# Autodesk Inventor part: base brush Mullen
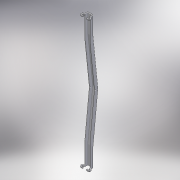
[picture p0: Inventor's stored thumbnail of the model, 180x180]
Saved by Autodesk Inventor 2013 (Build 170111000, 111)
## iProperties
Shininess: 20.0
Length Units: 11269
Angle Units: 11279
Time Units: 11290
Mass Units: 11283
Length Display Precision: 3
Angle Display Precision: 2
Created: 2002-03
Part Number: base brush Mullen
Document SubType Name: Modeling
Designer: =<Author>
Density: 1 g/cm^3
Material: Generic
Description: =<Part Number>
Density: 0.0
Volumn: 0.0
Area: 0.0
PropertySet Name: Model Information
Control State: 0
Master: False
Checked Out: True
Last Check In Date: 2008-10-15
Checked Out Date: 2008-10-15
Author: LAlexey
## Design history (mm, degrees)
sketch "Sketch1"
  geometry: L1 (0, 121.295)-(-5.969, 63.112); L2 (0, 3.705)-(-5.969, 61.888); L3 (0, -27.5)-(0, 3.705); L4 (0, -27.5)-(-4, -27.5); L5 (-4, -27.5)-(-4, -2.5); L6 (-4, -2.5)-(-10.557, 61.417); L7 (-4, 127.5)-(-10.557, 63.583); L8 (-4, 152.5)-(-4, 127.5); L9 (0, 152.5)-(-4, 152.5); L10 (0, 121.295)-(0, 152.5); A1 r 6 centre (0, 62.5) between (-5.969, 63.112) and (-5.969, 61.888); A2 r 10.612 centre (0, 62.5) between (-10.557, 63.583) and (-10.557, 61.417)
  constraints: 20 end point, 4 point on circle, 4 tangent, 4 vertical, 2 centre point, 2 collinear, 2 horizontal, 2 parallel, 1 concentric, 1 other
  dimensions: "d1" = 180 distance of L4.end L8.start; "d3" = 25 distance of L4.end L5.end; "d5" = 25 distance of L8.start L7.start; "d7" = 90 distance of L9.start A2.centre; "d9" = 6 radius of A1; "d11" = 4 distance of L4.end L3.start; "d13" = 4 horizontal distance of L7.start A2.centre
extrude "ExtrusionBlind1" new body sketch "Sketch1" distance "d14" = 8; taper "d15" = 0 deg
fillet "Fillet1" dims "d16" = 1.5
shell "Shell1" dims "d17" = 1
sketch "Sketch2"
  geometry: L1 (63, 6.982)-(63, 5.979); L2 (62, 6.982)-(62, 5.979); C1 r 6 at (62.5, 0); A1 r 6 centre (62.5, 0) between (63, 5.979) and (62, 5.979); A2 r 7 centre (62.5, 0) between (63, 6.982) and (62, 6.982)
  constraints: 4 end point, 4 point on circle, 3 centre point, 2 vertical, 1 coincident, 1 concentric
  dimensions: "d22" = 1 distance of L1.end L2.end; "d24" = 0.5 horizontal distance of L1.end A2.centre
extrude "ExtrusionThru1" cut sketch "Sketch2" stored distance "d25" = 0.13; taper "d26" = 0 deg
sketch "Sketch3"
  geometry: L1 (-8.5, -3.5)-(-6.5, -3.5); L2 (-8, 0)-(-7, 0); L3 (-8.5, -4.5)-(-6.5, -4.5); L4 (-6.5, -3.5)-(-6.5, -4.5); L5 (0, 0)-(-1, 0) reference; A1 r 1 centre (-8.5, -2.5) between (-8.5, -1.5) and (-8.5, -3.5); A2 r 1.5 centre (-8.5, 0) between (-8.5, -1.5) and (-7, 0); A3 r 0.5 centre (-8.5, 0) between (-8.5, -0.5) and (-8, 0); A4 r 2 centre (-8.5, -2.5) between (-8.5, -0.5) and (-8.5, -4.5)
  constraints: 8 end point, 8 point on circle, 4 centre point, 3 horizontal, 2 concentric, 2 tangent, 1 collinear, 1 vertical
  dimensions: "d28" = 1 radius of A1; "d30" = 2 radius of A4; "d32" = 2 horizontal distance of L1.end A4.centre; "d34" = 1 distance of L1.end L3.end; "d36" = 1.5 radius of A2; "d38" = 1 distance of L2.end L2.start
extrude "ExtrusionBlind2" join sketch "Sketch3" distance "d39" = 1.5; taper "d40" = 0 deg
sketch "Sketch4"
  geometry: L1 (0.493, -3.645)-(-1.507, -3.645); L2 (0.015, 0)-(-1, 0); L3 (0.493, -4.645)-(-1.507, -4.645); L4 (-1.507, -3.645)-(-1.507, -4.645); A1 r 1 centre (0.493, -2.645) between (0.493, -3.645) and (0.493, -1.645); A2 r 1.5 centre (0.493, -0.145) between (-1, 0) and (0.493, -1.645); A3 r 0.5 centre (0.493, -0.145) between (0.015, 0) and (0.493, -0.645); A4 r 2 centre (0.493, -2.645) between (0.493, -4.645) and (0.493, -0.645)
  constraints: 8 end point, 8 point on circle, 4 centre point, 3 horizontal, 3 tangent, 2 concentric, 1 vertical
  dimensions: "d42" = 2 distance of L3.end L3.start; "d44" = 2 radius of A4; "d46" = 1 radius of A1; "d48" = 1.5 radius of A2; "d50" = 0.5 radius of A3; "d52" = 0 vertical distance of L2.start L2.end (derived)
extrude "ExtrusionBlind3" join sketch "Sketch4" distance "d53" = 1.5; taper "d54" = 0 deg
sketch "Sketch5"
  geometry: L1 (8.493, -3.645)-(6.493, -3.645); L2 (8.015, 0)-(7, 0); L3 (8.493, -4.645)-(6.493, -4.645); L4 (6.493, -3.645)-(6.493, -4.645); L5 (0, 0)-(1, 0) reference; A1 r 1 centre (8.493, -2.645) between (8.493, -3.645) and (8.493, -1.645); A2 r 1.5 centre (8.493, -0.145) between (7, 0) and (8.493, -1.645); A3 r 0.5 centre (8.493, -0.145) between (8.015, 0) and (8.493, -0.645); A4 r 2 centre (8.493, -2.645) between (8.493, -4.645) and (8.493, -0.645)
  constraints: 8 end point, 8 point on circle, 4 centre point, 3 horizontal, 3 tangent, 2 concentric, 1 collinear, 1 vertical
  dimensions: "d56" = 2 distance of L3.end L3.start; "d58" = 2 radius of A4; "d60" = 1 radius of A1; "d62" = 1.5 radius of A2; "d64" = 0.5 radius of A3
extrude "ExtrusionBlind4" join sketch "Sketch5" distance "d65" = 1.5; taper "d66" = 0 deg
sketch "Sketch6"
  geometry: L1 (-0.5, -3.5)-(1.5, -3.5); L2 (0, 0)-(1, 0); L3 (-0.5, -4.5)-(1.5, -4.5); L4 (1.5, -3.5)-(1.5, -4.5); L5 (0, 0)-(1, 0) reference; A1 r 1 centre (-0.5, -2.5) between (-0.5, -1.5) and (-0.5, -3.5); A2 r 1.5 centre (-0.5, 0) between (-0.5, -1.5) and (1, 0); A3 r 0.5 centre (-0.5, 0) between (-0.5, -0.5) and (0, 0); A4 r 2 centre (-0.5, -2.5) between (-0.5, -0.5) and (-0.5, -4.5)
  constraints: 8 end point, 8 point on circle, 4 centre point, 3 horizontal, 2 concentric, 2 tangent, 1 collinear, 1 vertical
  dimensions: "d68" = 1 radius of A1; "d70" = 2 radius of A4; "d72" = 2 horizontal distance of L1.end A4.centre; "d74" = 1 distance of L1.end L3.end; "d76" = 1.5 radius of A2
extrude "ExtrusionBlind5" join sketch "Sketch6" distance "d77" = 1.5; taper "d78" = 0 deg
body "Solid1"
other parameters: "d2" = 25 (derived), "d4" = 25 (derived), "d8" = 6 (derived), "d10" = 4 (derived), "d12" = 4 (derived), "d18" = 0, "d19" = 0, "d20" = 0, "d21" = 1 (derived), "d23" = 0.5 (derived), "d27" = 1 (derived), "d29" = 2 (derived), "d31" = 2 (derived), "d33" = 1 (derived), "d35" = 1.5 (derived), "d37" = 1 (derived), "d41" = 2 (derived), "d43" = 2 (derived), "d45" = 1 (derived), "d47" = 1.5 (derived), "d49" = 0.5 (derived), "d51" = 0 (derived), "d55" = 2 (derived), "d57" = 2 (derived), "d59" = 1 (derived), "d61" = 1.5 (derived), "d63" = 0.5 (derived), "d67" = 1 (derived), "d69" = 2 (derived), "d71" = 2 (derived), "d73" = 1 (derived), "d75" = 1.5 (derived)
